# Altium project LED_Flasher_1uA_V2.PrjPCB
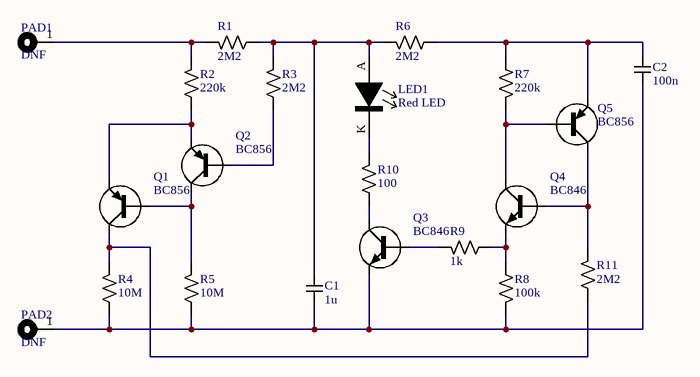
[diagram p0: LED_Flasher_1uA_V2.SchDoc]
1 sheet, 21 parts. Net scope: global (net labels, ports and power ports of the same name join across sheets).
Board file: LED_Flasher_1uA_V2.PcbDoc

## Sheet LED_Flasher_1uA_V2.SchDoc
size A4

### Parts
C1  1u  [1206]
C2  100n  [0805]
LED1  Red LED  [LED5mm-reducedpads]
PAD1  DNF  [PAD2MM+1MMHOLE]
PAD2  DNF  [PAD2MM+1MMHOLE]
Q1  BC856  [SOT23-3]
Q2  BC856  [SOT23-3]
Q3  BC846  [SOT23-3]
Q4  BC846  [SOT23-3]
Q5  BC856  [SOT23-3]
R1  2M2  [0805-res]
R2  220k  [0805-res]
R3  2M2  [0805-res]
R4  10M  [0805-res]
R5  10M  [0805-res]
R6  2M2  [0805-res]
R7  220k  [0805-res]
R8  100k  [0805-res]
R9  1k  [0805-res]
R10  100  [0805-res]
R11  2M2  [0805-res]

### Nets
NetC1_1: C1.1 C2.2 PAD2.1 Q3.2(E) R4.1 R5.1 R8.2
NetC1_2: C1.2 LED1.A R1.1 R3.2 R6.2
NetC2_1: C2.1 Q5.2(E) R6.1 R7.1
NetLED1_K: LED1.K R10.2
NetPAD1_1: PAD1.1 R1.2 R2.2
NetQ1_1: Q1.1(B) Q2.3(C) R5.2
NetQ1_2: Q1.2(E) Q2.2(E) R2.1
NetQ1_3: Q1.3(C) R4.2 R11.1
NetQ2_1: Q2.1(B) R3.1
NetQ3_1: Q3.1(B) R9.2
NetQ3_3: Q3.3(C) R10.1
NetQ4_1: Q4.1(B) Q5.3(C) R11.2
NetQ4_2: Q4.2(E) R8.1 R9.1
NetQ4_3: Q4.3(C) Q5.1(B) R7.2

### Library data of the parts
C1 = CAP 1206
C2 = CAP 0805
LED1 = LED
PAD1 PAD2 = Pad 2mm 1mm hole: A single pad.
Q1 Q2 Q5 = Transistor_BC856: BC856 PNP transistor
Q3 Q4 = Transistor_BC846: BC846 NPN transistor
R1-R11 = RES 0805: Resistor 0805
